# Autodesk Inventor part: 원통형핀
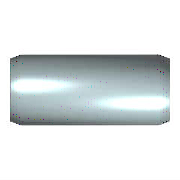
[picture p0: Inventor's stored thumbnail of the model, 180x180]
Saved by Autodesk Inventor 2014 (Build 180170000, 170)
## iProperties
IsCustomPart: 1
Created: 2012-02
Part Number: 원통형핀
Material: 강철, 연강
Description: 평행 핀
Document SubType Name: Modeling
Standard: KS B 1320
Designer: mduedu
Standards Organization: KS
Language: ko-KR
Size Designation: B 2 x  14
Categories: <MemberInstance><Categories><Category DisplayName="조임쇠" InternalName="e4da775c-781d-43d5-af7c-5136215cf5a6" Mnemonic="FSTN"><Category DisplayName="핀" InternalNa
Density: 1 g/cm^3
Appearance: Blue - Wall Paint - Glossy
Author: mduedu
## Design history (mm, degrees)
sketch "스케치"
  geometry: C1 r 1 at (0, 0); 1 further point
  constraints: 1 centre point, 1 coincident
  dimensions: "d1" = 2 diameter of C1 (= NND)
extrude "본체" new body sketch "스케치" distance "d2" = 14 (= NLG); taper "d3" = 0 deg
chamfer "스케치2" distance "d8" = 0.35 (= PHH); stored, may be unused: angle "d9" = 15 deg (= FAWI), second distance "d12" = 0.35 (= PHH)
node "작업 평면1"
body "Solid1"
chamfer "모따기1" distance "d4" = 0.35 (= PHH); stored, may be unused: angle "d5" = 15 deg (= FAWI), second distance "d11" = 0.35 (= PHH)
other parameters: "NND" = 2 [user parameter; used in 1 equation term], "NLG" = 14 [user parameter; used in 1 equation term], "PHH" = 0.35 [user parameter; used in 4 equation terms], "FAWI" = 15 deg [user parameter; used in 2 equation terms], "d13" = 0, "d15" = 0, "d16" = 0, "KAH" = 0.25 [user parameter]
